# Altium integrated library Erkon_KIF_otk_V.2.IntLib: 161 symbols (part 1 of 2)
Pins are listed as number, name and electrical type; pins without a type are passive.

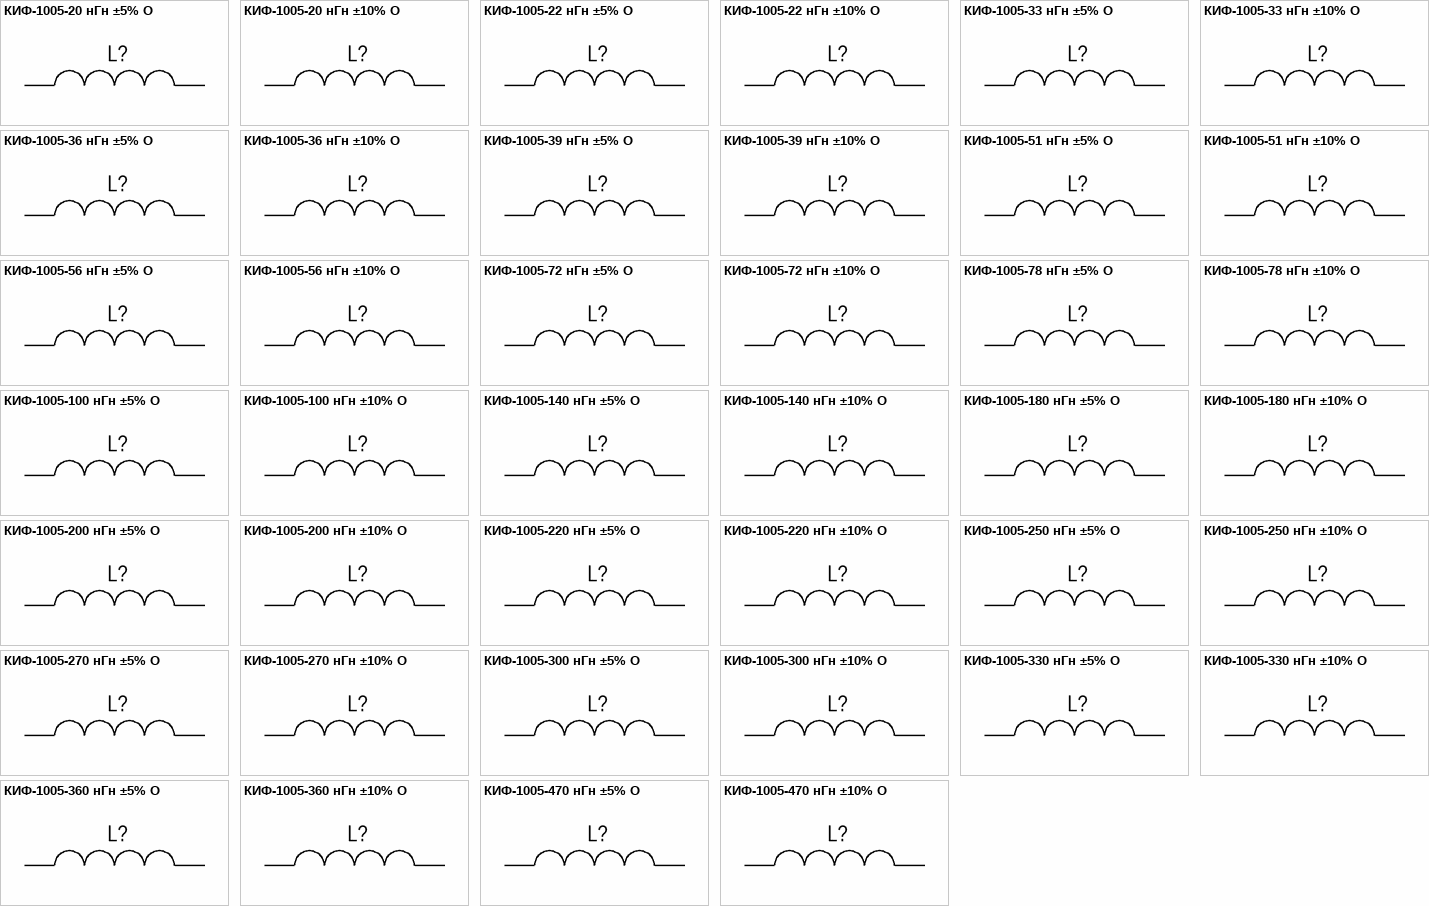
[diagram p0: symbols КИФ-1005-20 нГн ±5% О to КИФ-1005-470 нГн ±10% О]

## КИФ-1005-20 нГн ±5% О
designator L?, comment 20 нГн ±5%  (value not drawn)
Катушка индуктивности с ферритовым сердечником; Номиналиная индуктивность: 20 нГн; Добротность, не менее: 8; Резонансная частота, не менее: 2.6 ГГц; Сопротивление обмотки постоянноми току, не более: 0.07 Ом; Допустимый ток обмотки: 1600 мА; Диапазон рабочих температур: от -60 до +125 ℃; Упаковка: Катушка и лента; Типоразмер: 1005 (0402); Технология монтажа: SMT; Изготовитель: АО "НПО "ЭРКОН"
footprint КИФ-1005_О (Катушка индуктивности с ферритовым сердечником типоразмер 1005(0402))
pins: 1, 2

## КИФ-1005-20 нГн ±10% О
designator L?, comment 20 нГн ±10%  (value not drawn)
Катушка индуктивности с ферритовым сердечником; Номиналиная индуктивность: 20 нГн; Добротность, не менее: 8; Резонансная частота, не менее: 2.6 ГГц; Сопротивление обмотки постоянноми току, не более: 0.07 Ом; Допустимый ток обмотки: 1600 мА; Диапазон рабочих температур: от -60 до +125 ℃; Упаковка: Катушка и лента; Типоразмер: 1005 (0402); Технология монтажа: SMT; Изготовитель: АО "НПО "ЭРКОН"
footprint КИФ-1005_О (Катушка индуктивности с ферритовым сердечником типоразмер 1005(0402))
pins: 1, 2

## КИФ-1005-22 нГн ±5% О
designator L?, comment 22 нГн ±5%  (value not drawn)
Катушка индуктивности с ферритовым сердечником; Номиналиная индуктивность: 22 нГн; Добротность, не менее: 8; Резонансная частота, не менее: 2.5 ГГц; Сопротивление обмотки постоянноми току, не более: 0.08 Ом; Допустимый ток обмотки: 1300 мА; Диапазон рабочих температур: от -60 до +125 ℃; Упаковка: Катушка и лента; Типоразмер: 1005 (0402); Технология монтажа: SMT; Изготовитель: АО "НПО "ЭРКОН"
footprint КИФ-1005_О (Катушка индуктивности с ферритовым сердечником типоразмер 1005(0402))
pins: 1, 2

## КИФ-1005-22 нГн ±10% О
designator L?, comment 22 нГн ±10%  (value not drawn)
Катушка индуктивности с ферритовым сердечником; Номиналиная индуктивность: 22 нГн; Добротность, не менее: 8; Резонансная частота, не менее: 2.5 ГГц; Сопротивление обмотки постоянноми току, не более: 0.08 Ом; Допустимый ток обмотки: 1300 мА; Диапазон рабочих температур: от -60 до +125 ℃; Упаковка: Катушка и лента; Типоразмер: 1005 (0402); Технология монтажа: SMT; Изготовитель: АО "НПО "ЭРКОН"
footprint КИФ-1005_О (Катушка индуктивности с ферритовым сердечником типоразмер 1005(0402))
pins: 1, 2

## КИФ-1005-33 нГн ±5% О
designator L?, comment 33 нГн ±5%  (value not drawn)
Катушка индуктивности с ферритовым сердечником; Номиналиная индуктивность: 33 нГн; Добротность, не менее: 8; Резонансная частота, не менее: 2.3 ГГц; Сопротивление обмотки постоянноми току, не более: 0.08 Ом; Допустимый ток обмотки: 1400 мА; Диапазон рабочих температур: от -60 до +125 ℃; Упаковка: Катушка и лента; Типоразмер: 1005 (0402); Технология монтажа: SMT; Изготовитель: АО "НПО "ЭРКОН"
footprint КИФ-1005_О (Катушка индуктивности с ферритовым сердечником типоразмер 1005(0402))
pins: 1, 2

## КИФ-1005-33 нГн ±10% О
designator L?, comment 33 нГн ±10%  (value not drawn)
Катушка индуктивности с ферритовым сердечником; Номиналиная индуктивность: 33 нГн; Добротность, не менее: 8; Резонансная частота, не менее: 2.3 ГГц; Сопротивление обмотки постоянноми току, не более: 0.08 Ом; Допустимый ток обмотки: 1400 мА; Диапазон рабочих температур: от -60 до +125 ℃; Упаковка: Катушка и лента; Типоразмер: 1005 (0402); Технология монтажа: SMT; Изготовитель: АО "НПО "ЭРКОН"
footprint КИФ-1005_О (Катушка индуктивности с ферритовым сердечником типоразмер 1005(0402))
pins: 1, 2

## КИФ-1005-36 нГн ±5% О
designator L?, comment 36 нГн ±5%  (value not drawn)
Катушка индуктивности с ферритовым сердечником; Номиналиная индуктивность: 36 нГн; Добротность, не менее: 8; Резонансная частота, не менее: 2.3 ГГц; Сопротивление обмотки постоянноми току, не более: 0.1 Ом; Допустимый ток обмотки: 1300 мА; Диапазон рабочих температур: от -60 до +125 ℃; Упаковка: Катушка и лента; Типоразмер: 1005 (0402); Технология монтажа: SMT; Изготовитель: АО "НПО "ЭРКОН"
footprint КИФ-1005_О (Катушка индуктивности с ферритовым сердечником типоразмер 1005(0402))
pins: 1, 2

## КИФ-1005-36 нГн ±10% О
designator L?, comment 36 нГн ±10%  (value not drawn)
Катушка индуктивности с ферритовым сердечником; Номиналиная индуктивность: 36 нГн; Добротность, не менее: 8; Резонансная частота, не менее: 2.3 ГГц; Сопротивление обмотки постоянноми току, не более: 0.1 Ом; Допустимый ток обмотки: 1300 мА; Диапазон рабочих температур: от -60 до +125 ℃; Упаковка: Катушка и лента; Типоразмер: 1005 (0402); Технология монтажа: SMT; Изготовитель: АО "НПО "ЭРКОН"
footprint КИФ-1005_О (Катушка индуктивности с ферритовым сердечником типоразмер 1005(0402))
pins: 1, 2

## КИФ-1005-39 нГн ±5% О
designator L?, comment 39 нГн ±5%  (value not drawn)
Катушка индуктивности с ферритовым сердечником; Номиналиная индуктивность: 39 нГн; Добротность, не менее: 8; Резонансная частота, не менее: 2.2 ГГц; Сопротивление обмотки постоянноми току, не более: 0.14 Ом; Допустимый ток обмотки: 830 мА; Диапазон рабочих температур: от -60 до +125 ℃; Упаковка: Катушка и лента; Типоразмер: 1005 (0402); Технология монтажа: SMT; Изготовитель: АО "НПО "ЭРКОН"
footprint КИФ-1005_О (Катушка индуктивности с ферритовым сердечником типоразмер 1005(0402))
pins: 1, 2

## КИФ-1005-39 нГн ±10% О
designator L?, comment 39 нГн ±10%  (value not drawn)
Катушка индуктивности с ферритовым сердечником; Номиналиная индуктивность: 39 нГн; Добротность, не менее: 8; Резонансная частота, не менее: 2.2 ГГц; Сопротивление обмотки постоянноми току, не более: 0.14 Ом; Допустимый ток обмотки: 830 мА; Диапазон рабочих температур: от -60 до +125 ℃; Упаковка: Катушка и лента; Типоразмер: 1005 (0402); Технология монтажа: SMT; Изготовитель: АО "НПО "ЭРКОН"
footprint КИФ-1005_О (Катушка индуктивности с ферритовым сердечником типоразмер 1005(0402))
pins: 1, 2

## КИФ-1005-51 нГн ±5% О
designator L?, comment 51 нГн ±5%  (value not drawn)
Катушка индуктивности с ферритовым сердечником; Номиналиная индуктивность: 51 нГн; Добротность, не менее: 8; Резонансная частота, не менее: 1.93 ГГц; Сопротивление обмотки постоянноми току, не более: 0.11 Ом; Допустимый ток обмотки: 1100 мА; Диапазон рабочих температур: от -60 до +125 ℃; Упаковка: Катушка и лента; Типоразмер: 1005 (0402); Технология монтажа: SMT; Изготовитель: АО "НПО "ЭРКОН"
footprint КИФ-1005_О (Катушка индуктивности с ферритовым сердечником типоразмер 1005(0402))
pins: 1, 2

## КИФ-1005-51 нГн ±10% О
designator L?, comment 51 нГн ±10%  (value not drawn)
Катушка индуктивности с ферритовым сердечником; Номиналиная индуктивность: 51 нГн; Добротность, не менее: 8; Резонансная частота, не менее: 1.93 ГГц; Сопротивление обмотки постоянноми току, не более: 0.11 Ом; Допустимый ток обмотки: 1100 мА; Диапазон рабочих температур: от -60 до +125 ℃; Упаковка: Катушка и лента; Типоразмер: 1005 (0402); Технология монтажа: SMT; Изготовитель: АО "НПО "ЭРКОН"
footprint КИФ-1005_О (Катушка индуктивности с ферритовым сердечником типоразмер 1005(0402))
pins: 1, 2

## КИФ-1005-56 нГн ±5% О
designator L?, comment 56 нГн ±5%  (value not drawn)
Катушка индуктивности с ферритовым сердечником; Номиналиная индуктивность: 56 нГн; Добротность, не менее: 8; Резонансная частота, не менее: 1.90 ГГц; Сопротивление обмотки постоянноми току, не более: 0.12 Ом; Допустимый ток обмотки: 1000 мА; Диапазон рабочих температур: от -60 до +125 ℃; Упаковка: Катушка и лента; Типоразмер: 1005 (0402); Технология монтажа: SMT; Изготовитель: АО "НПО "ЭРКОН"
footprint КИФ-1005_О (Катушка индуктивности с ферритовым сердечником типоразмер 1005(0402))
pins: 1, 2

## КИФ-1005-56 нГн ±10% О
designator L?, comment 56 нГн ±10%  (value not drawn)
Катушка индуктивности с ферритовым сердечником; Номиналиная индуктивность: 56 нГн; Добротность, не менее: 8; Резонансная частота, не менее: 1.90 ГГц; Сопротивление обмотки постоянноми току, не более: 0.12 Ом; Допустимый ток обмотки: 1000 мА; Диапазон рабочих температур: от -60 до +125 ℃; Упаковка: Катушка и лента; Типоразмер: 1005 (0402); Технология монтажа: SMT; Изготовитель: АО "НПО "ЭРКОН"
footprint КИФ-1005_О (Катушка индуктивности с ферритовым сердечником типоразмер 1005(0402))
pins: 1, 2

## КИФ-1005-72 нГн ±5% О
designator L?, comment 72 нГн ±5%  (value not drawn)
Катушка индуктивности с ферритовым сердечником; Номиналиная индуктивность: 72 нГн; Добротность, не менее: 8; Резонансная частота, не менее: 1.65ГГц; Сопротивление обмотки постоянноми току, не более: 0.12 Ом; Допустимый ток обмотки: 1000 мА; Диапазон рабочих температур: от -60 до +125 ℃; Упаковка: Катушка и лента; Типоразмер: 1005 (0402); Технология монтажа: SMT; Изготовитель: АО "НПО "ЭРКОН"
footprint КИФ-1005_О (Катушка индуктивности с ферритовым сердечником типоразмер 1005(0402))
pins: 1, 2

## КИФ-1005-72 нГн ±10% О
designator L?, comment 72 нГн ±10%  (value not drawn)
Катушка индуктивности с ферритовым сердечником; Номиналиная индуктивность: 72 нГн; Добротность, не менее: 8; Резонансная частота, не менее: 1.65ГГц; Сопротивление обмотки постоянноми току, не более: 0.12 Ом; Допустимый ток обмотки: 1000 мА; Диапазон рабочих температур: от -60 до +125 ℃; Упаковка: Катушка и лента; Типоразмер: 1005 (0402); Технология монтажа: SMT; Изготовитель: АО "НПО "ЭРКОН"
footprint КИФ-1005_О (Катушка индуктивности с ферритовым сердечником типоразмер 1005(0402))
pins: 1, 2

## КИФ-1005-78 нГн ±5% О
designator L?, comment 78 нГн ±5%  (value not drawn)
Катушка индуктивности с ферритовым сердечником; Номиналиная индуктивность: 78 нГн; Добротность, не менее: 8; Резонансная частота, не менее: 1.6 ГГц; Сопротивление обмотки постоянноми току, не более: 0.16 Ом; Допустимый ток обмотки: 970 мА; Диапазон рабочих температур: от -60 до +125 ℃; Упаковка: Катушка и лента; Типоразмер: 1005 (0402); Технология монтажа: SMT; Изготовитель: АО "НПО "ЭРКОН"
footprint КИФ-1005_О (Катушка индуктивности с ферритовым сердечником типоразмер 1005(0402))
pins: 1, 2

## КИФ-1005-78 нГн ±10% О
designator L?, comment 78 нГн ±10%  (value not drawn)
Катушка индуктивности с ферритовым сердечником; Номиналиная индуктивность: 78 нГн; Добротность, не менее: 8; Резонансная частота, не менее: 1.6 ГГц; Сопротивление обмотки постоянноми току, не более: 0.16 Ом; Допустимый ток обмотки: 970 мА; Диапазон рабочих температур: от -60 до +125 ℃; Упаковка: Катушка и лента; Типоразмер: 1005 (0402); Технология монтажа: SMT; Изготовитель: АО "НПО "ЭРКОН"
footprint КИФ-1005_О (Катушка индуктивности с ферритовым сердечником типоразмер 1005(0402))
pins: 1, 2

## КИФ-1005-100 нГн ±5% О
designator L?, comment 100 нГн ±5%  (value not drawn)
Катушка индуктивности с ферритовым сердечником; Номиналиная индуктивность: 100 нГн; Добротность, не менее: 8; Резонансная частота, не менее: 1.4 ГГц; Сопротивление обмотки постоянноми току, не более: 0.19 Ом; Допустимый ток обмотки: 900 мА; Диапазон рабочих температур: от -60 до +125 ℃; Упаковка: Катушка и лента; Типоразмер: 1005 (0402); Технология монтажа: SMT; Изготовитель: АО "НПО "ЭРКОН"
footprint КИФ-1005_О (Катушка индуктивности с ферритовым сердечником типоразмер 1005(0402))
pins: 1, 2

## КИФ-1005-100 нГн ±10% О
designator L?, comment 100 нГн ±10%  (value not drawn)
Катушка индуктивности с ферритовым сердечником; Номиналиная индуктивность: 100 нГн; Добротность, не менее: 8; Резонансная частота, не менее: 1.4 ГГц; Сопротивление обмотки постоянноми току, не более: 0.19 Ом; Допустимый ток обмотки: 900 мА; Диапазон рабочих температур: от -60 до +125 ℃; Упаковка: Катушка и лента; Типоразмер: 1005 (0402); Технология монтажа: SMT; Изготовитель: АО "НПО "ЭРКОН"
footprint КИФ-1005_О (Катушка индуктивности с ферритовым сердечником типоразмер 1005(0402))
pins: 1, 2

## КИФ-1005-140 нГн ±5% О
designator L?, comment 140 нГн ±5%  (value not drawn)
Катушка индуктивности с ферритовым сердечником; Номиналиная индуктивность: 140 нГн; Добротность, не менее: 8; Резонансная частота, не менее: 1.22 ГГц; Сопротивление обмотки постоянноми току, не более: 0.31 Ом; Допустимый ток обмотки: 630 мА; Диапазон рабочих температур: от -60 до +125 ℃; Упаковка: Катушка и лента; Типоразмер: 1005 (0402); Технология монтажа: SMT; Изготовитель: АО "НПО "ЭРКОН"
footprint КИФ-1005_О (Катушка индуктивности с ферритовым сердечником типоразмер 1005(0402))
pins: 1, 2

## КИФ-1005-140 нГн ±10% О
designator L?, comment 140 нГн ±10%  (value not drawn)
Катушка индуктивности с ферритовым сердечником; Номиналиная индуктивность: 140 нГн; Добротность, не менее: 8; Резонансная частота, не менее: 1.22 ГГц; Сопротивление обмотки постоянноми току, не более: 0.31 Ом; Допустимый ток обмотки: 630 мА; Диапазон рабочих температур: от -60 до +125 ℃; Упаковка: Катушка и лента; Типоразмер: 1005 (0402); Технология монтажа: SMT; Изготовитель: АО "НПО "ЭРКОН"
footprint КИФ-1005_О (Катушка индуктивности с ферритовым сердечником типоразмер 1005(0402))
pins: 1, 2

## КИФ-1005-180 нГн ±5% О
designator L?, comment 180 нГн ±5%  (value not drawn)
Катушка индуктивности с ферритовым сердечником; Номиналиная индуктивность: 180 нГн; Добротность, не менее: 8; Резонансная частота, не менее: 1.15 ГГц; Сопротивление обмотки постоянноми току, не более: 0.34 Ом; Допустимый ток обмотки: 560 мА; Диапазон рабочих температур: от -60 до +125 ℃; Упаковка: Катушка и лента; Типоразмер: 1005 (0402); Технология монтажа: SMT; Изготовитель: АО "НПО "ЭРКОН"
footprint КИФ-1005_О (Катушка индуктивности с ферритовым сердечником типоразмер 1005(0402))
pins: 1, 2

## КИФ-1005-180 нГн ±10% О
designator L?, comment 180 нГн ±10%  (value not drawn)
Катушка индуктивности с ферритовым сердечником; Номиналиная индуктивность: 180 нГн; Добротность, не менее: 8; Резонансная частота, не менее: 1.15 ГГц; Сопротивление обмотки постоянноми току, не более: 0.34 Ом; Допустимый ток обмотки: 560 мА; Диапазон рабочих температур: от -60 до +125 ℃; Упаковка: Катушка и лента; Типоразмер: 1005 (0402); Технология монтажа: SMT; Изготовитель: АО "НПО "ЭРКОН"
footprint КИФ-1005_О (Катушка индуктивности с ферритовым сердечником типоразмер 1005(0402))
pins: 1, 2

## КИФ-1005-200 нГн ±5% О
designator L?, comment 200 нГн ±5%  (value not drawn)
Катушка индуктивности с ферритовым сердечником; Номиналиная индуктивность: 200 нГн; Добротность, не менее: 8; Резонансная частота, не менее: 1 ГГц; Сопротивление обмотки постоянноми току, не более: 0.53 Ом; Допустимый ток обмотки: 400 мА; Диапазон рабочих температур: от -60 до +125 ℃; Упаковка: Катушка и лента; Типоразмер: 1005 (0402); Технология монтажа: SMT; Изготовитель: АО "НПО "ЭРКОН"
footprint КИФ-1005_О (Катушка индуктивности с ферритовым сердечником типоразмер 1005(0402))
pins: 1, 2

## КИФ-1005-200 нГн ±10% О
designator L?, comment 200 нГн ±10%  (value not drawn)
Катушка индуктивности с ферритовым сердечником; Номиналиная индуктивность: 200 нГн; Добротность, не менее: 8; Резонансная частота, не менее: 1 ГГц; Сопротивление обмотки постоянноми току, не более: 0.53 Ом; Допустимый ток обмотки: 400 мА; Диапазон рабочих температур: от -60 до +125 ℃; Упаковка: Катушка и лента; Типоразмер: 1005 (0402); Технология монтажа: SMT; Изготовитель: АО "НПО "ЭРКОН"
footprint КИФ-1005_О (Катушка индуктивности с ферритовым сердечником типоразмер 1005(0402))
pins: 1, 2

## КИФ-1005-220 нГн ±5% О
designator L?, comment 220 нГн ±5%  (value not drawn)
Катушка индуктивности с ферритовым сердечником; Номиналиная индуктивность: 220 нГн; Добротность, не менее: 8; Резонансная частота, не менее: 1.15 ГГц; Сопротивление обмотки постоянноми току, не более: 0.64 Ом; Допустимый ток обмотки: 380 мА; Диапазон рабочих температур: от -60 до +125 ℃; Упаковка: Катушка и лента; Типоразмер: 1005 (0402); Технология монтажа: SMT; Изготовитель: АО "НПО "ЭРКОН"
footprint КИФ-1005_О (Катушка индуктивности с ферритовым сердечником типоразмер 1005(0402))
pins: 1, 2

## КИФ-1005-220 нГн ±10% О
designator L?, comment 220 нГн ±10%  (value not drawn)
Катушка индуктивности с ферритовым сердечником; Номиналиная индуктивность: 220 нГн; Добротность, не менее: 8; Резонансная частота, не менее: 1.15 ГГц; Сопротивление обмотки постоянноми току, не более: 0.64 Ом; Допустимый ток обмотки: 380 мА; Диапазон рабочих температур: от -60 до +125 ℃; Упаковка: Катушка и лента; Типоразмер: 1005 (0402); Технология монтажа: SMT; Изготовитель: АО "НПО "ЭРКОН"
footprint КИФ-1005_О (Катушка индуктивности с ферритовым сердечником типоразмер 1005(0402))
pins: 1, 2

## КИФ-1005-250 нГн ±5% О
designator L?, comment 250 нГн ±5%  (value not drawn)
Катушка индуктивности с ферритовым сердечником; Номиналиная индуктивность: 250 нГн; Добротность, не менее: 8; Резонансная частота, не менее: 0.9 ГГц; Сопротивление обмотки постоянноми току, не более: 0.43 Ом; Допустимый ток обмотки: 520 мА; Диапазон рабочих температур: от -60 до +125 ℃; Упаковка: Катушка и лента; Типоразмер: 1005 (0402); Технология монтажа: SMT; Изготовитель: АО "НПО "ЭРКОН"
footprint КИФ-1005_О (Катушка индуктивности с ферритовым сердечником типоразмер 1005(0402))
pins: 1, 2

## КИФ-1005-250 нГн ±10% О
designator L?, comment 250 нГн ±10%  (value not drawn)
Катушка индуктивности с ферритовым сердечником; Номиналиная индуктивность: 250 нГн; Добротность, не менее: 8; Резонансная частота, не менее: 0.9 ГГц; Сопротивление обмотки постоянноми току, не более: 0.43 Ом; Допустимый ток обмотки: 520 мА; Диапазон рабочих температур: от -60 до +125 ℃; Упаковка: Катушка и лента; Типоразмер: 1005 (0402); Технология монтажа: SMT; Изготовитель: АО "НПО "ЭРКОН"
footprint КИФ-1005_О (Катушка индуктивности с ферритовым сердечником типоразмер 1005(0402))
pins: 1, 2

## КИФ-1005-270 нГн ±5% О
designator L?, comment 270 нГн ±5%  (value not drawn)
Катушка индуктивности с ферритовым сердечником; Номиналиная индуктивность: 270 нГн; Добротность, не менее: 8; Резонансная частота, не менее: 0.86 ГГц; Сопротивление обмотки постоянноми току, не более: 0.66 Ом; Допустимый ток обмотки: 360 мА; Диапазон рабочих температур: от -60 до +125 ℃; Упаковка: Катушка и лента; Типоразмер: 1005 (0402); Технология монтажа: SMT; Изготовитель: АО "НПО "ЭРКОН"
footprint КИФ-1005_О (Катушка индуктивности с ферритовым сердечником типоразмер 1005(0402))
pins: 1, 2

## КИФ-1005-270 нГн ±10% О
designator L?, comment 270 нГн ±10%  (value not drawn)
Катушка индуктивности с ферритовым сердечником; Номиналиная индуктивность: 270 нГн; Добротность, не менее: 8; Резонансная частота, не менее: 0.86 ГГц; Сопротивление обмотки постоянноми току, не более: 0.66 Ом; Допустимый ток обмотки: 360 мА; Диапазон рабочих температур: от -60 до +125 ℃; Упаковка: Катушка и лента; Типоразмер: 1005 (0402); Технология монтажа: SMT; Изготовитель: АО "НПО "ЭРКОН"
footprint КИФ-1005_О (Катушка индуктивности с ферритовым сердечником типоразмер 1005(0402))
pins: 1, 2

## КИФ-1005-300 нГн ±5% О
designator L?, comment 300 нГн ±5%  (value not drawn)
Катушка индуктивности с ферритовым сердечником; Номиналиная индуктивность: 300 нГн; Добротность, не менее: 8; Резонансная частота, не менее: 0.86 ГГц; Сопротивление обмотки постоянноми току, не более: 0.5 Ом; Допустимый ток обмотки: 420 мА; Диапазон рабочих температур: от -60 до +125 ℃; Упаковка: Катушка и лента; Типоразмер: 1005 (0402); Технология монтажа: SMT; Изготовитель: АО "НПО "ЭРКОН"
footprint КИФ-1005_О (Катушка индуктивности с ферритовым сердечником типоразмер 1005(0402))
pins: 1, 2

## КИФ-1005-300 нГн ±10% О
designator L?, comment 300 нГн ±10%  (value not drawn)
Катушка индуктивности с ферритовым сердечником; Номиналиная индуктивность: 300 нГн; Добротность, не менее: 8; Резонансная частота, не менее: 0.86 ГГц; Сопротивление обмотки постоянноми току, не более: 0.5 Ом; Допустимый ток обмотки: 420 мА; Диапазон рабочих температур: от -60 до +125 ℃; Упаковка: Катушка и лента; Типоразмер: 1005 (0402); Технология монтажа: SMT; Изготовитель: АО "НПО "ЭРКОН"
footprint КИФ-1005_О (Катушка индуктивности с ферритовым сердечником типоразмер 1005(0402))
pins: 1, 2

## КИФ-1005-330 нГн ±5% О
designator L?, comment 330 нГн ±5%  (value not drawn)
Катушка индуктивности с ферритовым сердечником; Номиналиная индуктивность: 330 нГн; Добротность, не менее: 8; Резонансная частота, не менее: 0.82 ГГц; Сопротивление обмотки постоянноми току, не более: 0.67 Ом; Допустимый ток обмотки: 350 мА; Диапазон рабочих температур: от -60 до +125 ℃; Упаковка: Катушка и лента; Типоразмер: 1005 (0402); Технология монтажа: SMT; Изготовитель: АО "НПО "ЭРКОН"
footprint КИФ-1005_О (Катушка индуктивности с ферритовым сердечником типоразмер 1005(0402))
pins: 1, 2

## КИФ-1005-330 нГн ±10% О
designator L?, comment 330 нГн ±10%  (value not drawn)
Катушка индуктивности с ферритовым сердечником; Номиналиная индуктивность: 330 нГн; Добротность, не менее: 8; Резонансная частота, не менее: 0.82 ГГц; Сопротивление обмотки постоянноми току, не более: 0.67 Ом; Допустимый ток обмотки: 350 мА; Диапазон рабочих температур: от -60 до +125 ℃; Упаковка: Катушка и лента; Типоразмер: 1005 (0402); Технология монтажа: SMT; Изготовитель: АО "НПО "ЭРКОН"
footprint КИФ-1005_О (Катушка индуктивности с ферритовым сердечником типоразмер 1005(0402))
pins: 1, 2

## КИФ-1005-360 нГн ±5% О
designator L?, comment 360 нГн ±5%  (value not drawn)
Катушка индуктивности с ферритовым сердечником; Номиналиная индуктивность: 360 нГн; Добротность, не менее: 8; Резонансная частота, не менее: 0.81 ГГц; Сопротивление обмотки постоянноми току, не более: 0.75 Ом; Допустимый ток обмотки: 360 мА; Диапазон рабочих температур: от -60 до +125 ℃; Упаковка: Катушка и лента; Типоразмер: 1005 (0402); Технология монтажа: SMT; Изготовитель: АО "НПО "ЭРКОН"
footprint КИФ-1005_О (Катушка индуктивности с ферритовым сердечником типоразмер 1005(0402))
pins: 1, 2

## КИФ-1005-360 нГн ±10% О
designator L?, comment 360 нГн ±10%  (value not drawn)
Катушка индуктивности с ферритовым сердечником; Номиналиная индуктивность: 360 нГн; Добротность, не менее: 8; Резонансная частота, не менее: 0.81 ГГц; Сопротивление обмотки постоянноми току, не более: 0.75 Ом; Допустимый ток обмотки: 360 мА; Диапазон рабочих температур: от -60 до +125 ℃; Упаковка: Катушка и лента; Типоразмер: 1005 (0402); Технология монтажа: SMT; Изготовитель: АО "НПО "ЭРКОН"
footprint КИФ-1005_О (Катушка индуктивности с ферритовым сердечником типоразмер 1005(0402))
pins: 1, 2

## КИФ-1005-470 нГн ±5% О
designator L?, comment 470 нГн ±5%  (value not drawn)
Катушка индуктивности с ферритовым сердечником; Номиналиная индуктивность: 470 нГн; Добротность, не менее: 8; Резонансная частота, не менее: 0.7 ГГц; Сопротивление обмотки постоянноми току, не более: 1.42 Ом; Допустимый ток обмотки: 280 мА; Диапазон рабочих температур: от -60 до +125 ℃; Упаковка: Катушка и лента; Типоразмер: 1005 (0402); Технология монтажа: SMT; Изготовитель: АО "НПО "ЭРКОН"
footprint КИФ-1005_О (Катушка индуктивности с ферритовым сердечником типоразмер 1005(0402))
pins: 1, 2

## КИФ-1005-470 нГн ±10% О
designator L?, comment 470 нГн ±10%  (value not drawn)
Катушка индуктивности с ферритовым сердечником; Номиналиная индуктивность: 470 нГн; Допускаемое отклонение индуктивности: ±5%; Добротность, не менее: 8; Резонансная частота, не менее: 0.7 ГГц; Сопротивление обмотки постоянноми току, не более: 1.42 Ом; Допустимый ток обмотки: 280 мА; Диапазон рабочих температур: от -60 до +125 ℃; Упаковка: Катушка и лента; Типоразмер: 1005 (0402); Технология монтажа: SMT; Изготовитель: АО "НПО "ЭРКОН"
footprint КИФ-1005_О (Катушка индуктивности с ферритовым сердечником типоразмер 1005(0402))
pins: 1, 2


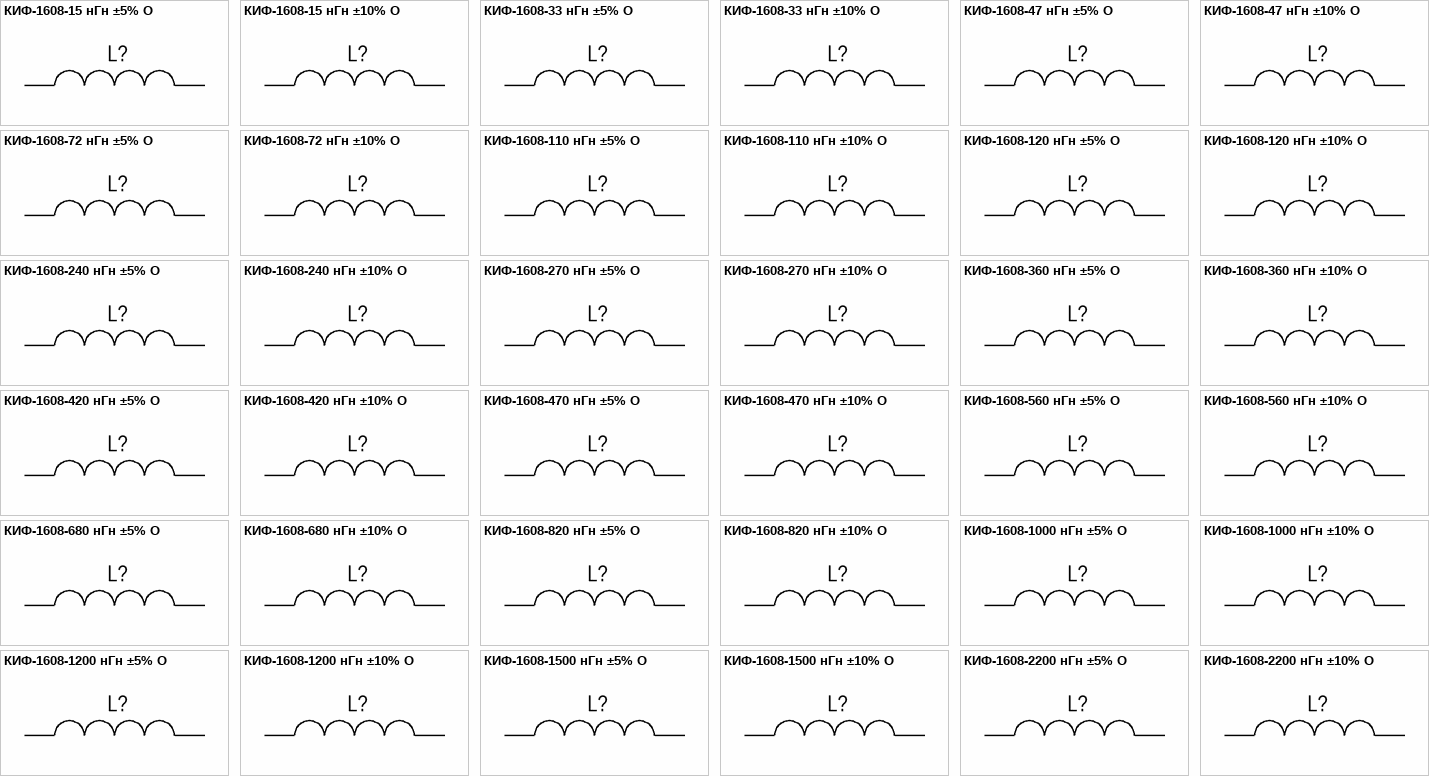
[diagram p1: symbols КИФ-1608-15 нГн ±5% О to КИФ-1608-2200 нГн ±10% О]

## КИФ-1608-15 нГн ±5% О
designator L?, comment 15 нГн ±5%  (value not drawn)
Катушка индуктивности с ферритовым сердечником; Номиналиная индуктивность: 15 нГн; Добротность, не менее: 10; Резонансная частота, не менее: 3.5 ГГц; Сопротивление обмотки постоянноми току, не более: 0.05 Ом; Допустимый ток обмотки: 2100 мА; Диапазон рабочих температур: от -60 до +125 ℃; Упаковка: Катушка и лента; Типоразмер: 1608 (0603); Технология монтажа: SMT; Изготовитель: АО "НПО "ЭРКОН"
footprint КИФ-1608-О (Катушка индуктивности с ферритовым сердечником типоразмер 1608(0805))
pins: 1, 2

## КИФ-1608-15 нГн ±10% О
designator L?, comment 15 нГн ±10%  (value not drawn)
Катушка индуктивности с ферритовым сердечником; Номиналиная индуктивность: 15 нГн; Добротность, не менее: 10; Резонансная частота, не менее: 3.5 ГГц; Сопротивление обмотки постоянноми току, не более: 0.05 Ом; Допустимый ток обмотки: 2100 мА; Диапазон рабочих температур: от -60 до +125 ℃; Упаковка: Катушка и лента; Типоразмер: 1608 (0603); Технология монтажа: SMT; Изготовитель: АО "НПО "ЭРКОН"
footprint КИФ-1608-О (Катушка индуктивности с ферритовым сердечником типоразмер 1608(0805))
pins: 1, 2

## КИФ-1608-33 нГн ±5% О
designator L?, comment 33 нГн ±5%  (value not drawn)
Катушка индуктивности с ферритовым сердечником; Номиналиная индуктивность: 33 нГн; Добротность, не менее: 10; Резонансная частота, не менее: 2.3 ГГц; Сопротивление обмотки постоянноми току, не более: 0.06 Ом; Допустимый ток обмотки: 1900 мА; Диапазон рабочих температур: от -60 до +125 ℃; Упаковка: Катушка и лента; Типоразмер: 1608 (0603); Технология монтажа: SMT; Изготовитель: АО "НПО "ЭРКОН"
footprint КИФ-1608-О (Катушка индуктивности с ферритовым сердечником типоразмер 1608(0805))
pins: 1, 2

## КИФ-1608-33 нГн ±10% О
designator L?, comment 33 нГн ±10%  (value not drawn)
Катушка индуктивности с ферритовым сердечником; Номиналиная индуктивность: 33 нГн; Добротность, не менее: 10; Резонансная частота, не менее: 2.3 ГГц; Сопротивление обмотки постоянноми току, не более: 0.06 Ом; Допустимый ток обмотки: 1900 мА; Диапазон рабочих температур: от -60 до +125 ℃; Упаковка: Катушка и лента; Типоразмер: 1608 (0603); Технология монтажа: SMT; Изготовитель: АО "НПО "ЭРКОН"
footprint КИФ-1608-О (Катушка индуктивности с ферритовым сердечником типоразмер 1608(0805))
pins: 1, 2

## КИФ-1608-47 нГн ±5% О
designator L?, comment 47 нГн ±5%  (value not drawn)
Катушка индуктивности с ферритовым сердечником; Номиналиная индуктивность: 47 нГн; Добротность, не менее: 10; Резонансная частота, не менее: 2.25 ГГц; Сопротивление обмотки постоянноми току, не более: 0.08 Ом; Допустимый ток обмотки: 1700 мА; Диапазон рабочих температур: от -60 до +125 ℃; Упаковка: Катушка и лента; Типоразмер: 1608 (0603); Технология монтажа: SMT; Изготовитель: АО "НПО "ЭРКОН"
footprint КИФ-1608-О (Катушка индуктивности с ферритовым сердечником типоразмер 1608(0805))
pins: 1, 2

## КИФ-1608-47 нГн ±10% О
designator L?, comment 47 нГн ±10%  (value not drawn)
Катушка индуктивности с ферритовым сердечником; Номиналиная индуктивность: 47 нГн; Добротность, не менее: 10; Резонансная частота, не менее: 2.25 ГГц; Сопротивление обмотки постоянноми току, не более: 0.08 Ом; Допустимый ток обмотки: 1700 мА; Диапазон рабочих температур: от -60 до +125 ℃; Упаковка: Катушка и лента; Типоразмер: 1608 (0603); Технология монтажа: SMT; Изготовитель: АО "НПО "ЭРКОН"
footprint КИФ-1608-О (Катушка индуктивности с ферритовым сердечником типоразмер 1608(0805))
pins: 1, 2

## КИФ-1608-72 нГн ±5% О
designator L?, comment 72 нГн ±5%  (value not drawn)
Катушка индуктивности с ферритовым сердечником; Номиналиная индуктивность: 72 нГн; Добротность, не менее: 10; Резонансная частота, не менее: 1.8 ГГц; Сопротивление обмотки постоянноми току, не более: 0.12 Ом; Допустимый ток обмотки: 1500 мА; Диапазон рабочих температур: от -60 до +125 ℃; Упаковка: Катушка и лента; Типоразмер: 1608 (0603); Технология монтажа: SMT; Изготовитель: АО "НПО "ЭРКОН"
footprint КИФ-1608-О (Катушка индуктивности с ферритовым сердечником типоразмер 1608(0805))
pins: 1, 2

## КИФ-1608-72 нГн ±10% О
designator L?, comment 72 нГн ±10%  (value not drawn)
Катушка индуктивности с ферритовым сердечником; Номиналиная индуктивность: 72 нГн; Добротность, не менее: 10; Резонансная частота, не менее: 1.8 ГГц; Сопротивление обмотки постоянноми току, не более: 0.12 Ом; Допустимый ток обмотки: 1500 мА; Диапазон рабочих температур: от -60 до +125 ℃; Упаковка: Катушка и лента; Типоразмер: 1608 (0603); Технология монтажа: SMT; Изготовитель: АО "НПО "ЭРКОН"
footprint КИФ-1608-О (Катушка индуктивности с ферритовым сердечником типоразмер 1608(0805))
pins: 1, 2

## КИФ-1608-110 нГн ±5% О
designator L?, comment 110 нГн ±5%  (value not drawn)
Катушка индуктивности с ферритовым сердечником; Номиналиная индуктивность: 110 нГн; Добротность, не менее: 10; Резонансная частота, не менее: 1.23 ГГц; Сопротивление обмотки постоянноми току, не более: 0.12 Ом; Допустимый ток обмотки: 1600 мА; Диапазон рабочих температур: от -60 до +125 ℃; Упаковка: Катушка и лента; Типоразмер: 1608 (0603); Технология монтажа: SMT; Изготовитель: АО "НПО "ЭРКОН"
footprint КИФ-1608-О (Катушка индуктивности с ферритовым сердечником типоразмер 1608(0805))
pins: 1, 2

## КИФ-1608-110 нГн ±10% О
designator L?, comment 110 нГн ±10%  (value not drawn)
Катушка индуктивности с ферритовым сердечником; Номиналиная индуктивность: 110 нГн; Добротность, не менее: 10; Резонансная частота, не менее: 1.23 ГГц; Сопротивление обмотки постоянноми току, не более: 0.12 Ом; Допустимый ток обмотки: 1600 мА; Диапазон рабочих температур: от -60 до +125 ℃; Упаковка: Катушка и лента; Типоразмер: 1608 (0603); Технология монтажа: SMT; Изготовитель: АО "НПО "ЭРКОН"
footprint КИФ-1608-О (Катушка индуктивности с ферритовым сердечником типоразмер 1608(0805))
pins: 1, 2

## КИФ-1608-120 нГн ±5% О
designator L?, comment 120 нГн ±5%  (value not drawn)
Катушка индуктивности с ферритовым сердечником; Номиналиная индуктивность: 120 нГн; Добротность, не менее: 10; Резонансная частота, не менее: 1.15 ГГц; Сопротивление обмотки постоянноми току, не более: 0.17 Ом; Допустимый ток обмотки: 1400 мА; Диапазон рабочих температур: от -60 до +125 ℃; Упаковка: Катушка и лента; Типоразмер: 1608 (0603); Технология монтажа: SMT; Изготовитель: АО "НПО "ЭРКОН"
footprint КИФ-1608-О (Катушка индуктивности с ферритовым сердечником типоразмер 1608(0805))
pins: 1, 2

## КИФ-1608-120 нГн ±10% О
designator L?, comment 120 нГн ±10%  (value not drawn)
Катушка индуктивности с ферритовым сердечником; Номиналиная индуктивность: 120 нГн; Добротность, не менее: 10; Резонансная частота, не менее: 1.15 ГГц; Сопротивление обмотки постоянноми току, не более: 0.17 Ом; Допустимый ток обмотки: 1400 мА; Диапазон рабочих температур: от -60 до +125 ℃; Упаковка: Катушка и лента; Типоразмер: 1608 (0603); Технология монтажа: SMT; Изготовитель: АО "НПО "ЭРКОН"
footprint КИФ-1608-О (Катушка индуктивности с ферритовым сердечником типоразмер 1608(0805))
pins: 1, 2

## КИФ-1608-240 нГн ±5% О
designator L?, comment 240 нГн ±5%  (value not drawn)
Катушка индуктивности с ферритовым сердечником; Номиналиная индуктивность: 240 нГн; Добротность, не менее: 10; Резонансная частота, не менее: 0.9 ГГц; Сопротивление обмотки постоянноми току, не более: 0.27 Ом; Допустимый ток обмотки: 850 мА; Диапазон рабочих температур: от -60 до +125 ℃; Упаковка: Катушка и лента; Типоразмер: 1608 (0603); Технология монтажа: SMT; Изготовитель: АО "НПО "ЭРКОН"
footprint КИФ-1608-О (Катушка индуктивности с ферритовым сердечником типоразмер 1608(0805))
pins: 1, 2

## КИФ-1608-240 нГн ±10% О
designator L?, comment 240 нГн ±10%  (value not drawn)
Катушка индуктивности с ферритовым сердечником; Номиналиная индуктивность: 240 нГн; Добротность, не менее: 10; Резонансная частота, не менее: 0.9 ГГц; Сопротивление обмотки постоянноми току, не более: 0.27 Ом; Допустимый ток обмотки: 850 мА; Диапазон рабочих температур: от -60 до +125 ℃; Упаковка: Катушка и лента; Типоразмер: 1608 (0603); Технология монтажа: SMT; Изготовитель: АО "НПО "ЭРКОН"
footprint КИФ-1608-О (Катушка индуктивности с ферритовым сердечником типоразмер 1608(0805))
pins: 1, 2

## КИФ-1608-270 нГн ±5% О
designator L?, comment 270 нГн ±5%  (value not drawn)
Катушка индуктивности с ферритовым сердечником; Номиналиная индуктивность: 270 нГн; Добротность, не менее: 10; Резонансная частота, не менее: 0.75 ГГц; Сопротивление обмотки постоянноми току, не более: 0.28 Ом; Допустимый ток обмотки: 680 мА; Диапазон рабочих температур: от -60 до +125 ℃; Упаковка: Катушка и лента; Типоразмер: 1608 (0603); Технология монтажа: SMT; Изготовитель: АО "НПО "ЭРКОН"
footprint КИФ-1608-О (Катушка индуктивности с ферритовым сердечником типоразмер 1608(0805))
pins: 1, 2

## КИФ-1608-270 нГн ±10% О
designator L?, comment 270 нГн ±10%  (value not drawn)
Катушка индуктивности с ферритовым сердечником; Номиналиная индуктивность: 270 нГн; Добротность, не менее: 10; Резонансная частота, не менее: 0.75 ГГц; Сопротивление обмотки постоянноми току, не более: 0.28 Ом; Допустимый ток обмотки: 680 мА; Диапазон рабочих температур: от -60 до +125 ℃; Упаковка: Катушка и лента; Типоразмер: 1608 (0603); Технология монтажа: SMT; Изготовитель: АО "НПО "ЭРКОН"
footprint КИФ-1608-О (Катушка индуктивности с ферритовым сердечником типоразмер 1608(0805))
pins: 1, 2

## КИФ-1608-360 нГн ±5% О
designator L?, comment 360 нГн ±5%  (value not drawn)
Катушка индуктивности с ферритовым сердечником; Номиналиная индуктивность: 360 нГн; Добротность, не менее: 10; Резонансная частота, не менее: 0.7 ГГц; Сопротивление обмотки постоянноми току, не более: 0.33 Ом; Допустимый ток обмотки: 650 мА; Диапазон рабочих температур: от -60 до +125 ℃; Упаковка: Катушка и лента; Типоразмер: 1608 (0603); Технология монтажа: SMT; Изготовитель: АО "НПО "ЭРКОН"
footprint КИФ-1608-О (Катушка индуктивности с ферритовым сердечником типоразмер 1608(0805))
pins: 1, 2

## КИФ-1608-360 нГн ±10% О
designator L?, comment 360 нГн ±10%  (value not drawn)
Катушка индуктивности с ферритовым сердечником; Номиналиная индуктивность: 360 нГн; Добротность, не менее: 10; Резонансная частота, не менее: 0.7 ГГц; Сопротивление обмотки постоянноми току, не более: 0.33 Ом; Допустимый ток обмотки: 650 мА; Диапазон рабочих температур: от -60 до +125 ℃; Упаковка: Катушка и лента; Типоразмер: 1608 (0603); Технология монтажа: SMT; Изготовитель: АО "НПО "ЭРКОН"
footprint КИФ-1608-О (Катушка индуктивности с ферритовым сердечником типоразмер 1608(0805))
pins: 1, 2

## КИФ-1608-420 нГн ±5% О
designator L?, comment 420 нГн ±5%  (value not drawn)
Катушка индуктивности с ферритовым сердечником; Номиналиная индуктивность: 420 нГн; Добротность, не менее: 10; Резонансная частота, не менее: 0.685 ГГц; Сопротивление обмотки постоянноми току, не более: 0.5 Ом; Допустимый ток обмотки: 610 мА; Диапазон рабочих температур: от -60 до +125 ℃; Упаковка: Катушка и лента; Типоразмер: 1608 (0603); Технология монтажа: SMT; Изготовитель: АО "НПО "ЭРКОН"
footprint КИФ-1608-О (Катушка индуктивности с ферритовым сердечником типоразмер 1608(0805))
pins: 1, 2

## КИФ-1608-420 нГн ±10% О
designator L?, comment 420 нГн ±10%  (value not drawn)
Катушка индуктивности с ферритовым сердечником; Номиналиная индуктивность: 420 нГн; Добротность, не менее: 10; Резонансная частота, не менее: 0.685 ГГц; Сопротивление обмотки постоянноми току, не более: 0.5 Ом; Допустимый ток обмотки: 610 мА; Диапазон рабочих температур: от -60 до +125 ℃; Упаковка: Катушка и лента; Типоразмер: 1608 (0603); Технология монтажа: SMT; Изготовитель: АО "НПО "ЭРКОН"
footprint КИФ-1608-О (Катушка индуктивности с ферритовым сердечником типоразмер 1608(0805))
pins: 1, 2

## КИФ-1608-470 нГн ±5% О
designator L?, comment 470 нГн ±5%  (value not drawn)
Катушка индуктивности с ферритовым сердечником; Номиналиная индуктивность: 470 нГн; Добротность, не менее: 10; Резонансная частота, не менее: 0.575 ГГц; Сопротивление обмотки постоянноми току, не более: 0.58 Ом; Допустимый ток обмотки: 610 мА; Диапазон рабочих температур: от -60 до +125 ℃; Упаковка: Катушка и лента; Типоразмер: 1608 (0603); Технология монтажа: SMT; Изготовитель: АО "НПО "ЭРКОН"
footprint КИФ-1608-О (Катушка индуктивности с ферритовым сердечником типоразмер 1608(0805))
pins: 1, 2

## КИФ-1608-470 нГн ±10% О
designator L?, comment 470 нГн ±10%  (value not drawn)
Катушка индуктивности с ферритовым сердечником; Номиналиная индуктивность: 470 нГн; Добротность, не менее: 10; Резонансная частота, не менее: 0.575 ГГц; Сопротивление обмотки постоянноми току, не более: 0.58 Ом; Допустимый ток обмотки: 610 мА; Диапазон рабочих температур: от -60 до +125 ℃; Упаковка: Катушка и лента; Типоразмер: 1608 (0603); Технология монтажа: SMT; Изготовитель: АО "НПО "ЭРКОН"
footprint КИФ-1608-О (Катушка индуктивности с ферритовым сердечником типоразмер 1608(0805))
pins: 1, 2

## КИФ-1608-560 нГн ±5% О
designator L?, comment 560 нГн ±5%  (value not drawn)
Катушка индуктивности с ферритовым сердечником; Номиналиная индуктивность: 560 нГн; Добротность, не менее: 10; Резонансная частота, не менее: 0.515 ГГц; Сопротивление обмотки постоянноми току, не более: 0.6 Ом; Допустимый ток обмотки: 530 мА; Диапазон рабочих температур: от -60 до +125 ℃; Упаковка: Катушка и лента; Типоразмер: 1608 (0603); Технология монтажа: SMT; Изготовитель: АО "НПО "ЭРКОН"
footprint КИФ-1608-О (Катушка индуктивности с ферритовым сердечником типоразмер 1608(0805))
pins: 1, 2

## КИФ-1608-560 нГн ±10% О
designator L?, comment 560 нГн ±10%  (value not drawn)
Катушка индуктивности с ферритовым сердечником; Номиналиная индуктивность: 560 нГн; Добротность, не менее: 10; Резонансная частота, не менее: 0.515 ГГц; Сопротивление обмотки постоянноми току, не более: 0.6 Ом; Допустимый ток обмотки: 530 мА; Диапазон рабочих температур: от -60 до +125 ℃; Упаковка: Катушка и лента; Типоразмер: 1608 (0603); Технология монтажа: SMT; Изготовитель: АО "НПО "ЭРКОН"
footprint КИФ-1608-О (Катушка индуктивности с ферритовым сердечником типоразмер 1608(0805))
pins: 1, 2

## КИФ-1608-680 нГн ±5% О
designator L?, comment 680 нГн ±5%  (value not drawn)
Катушка индуктивности с ферритовым сердечником; Номиналиная индуктивность: 680 нГн; Добротность, не менее: 10; Резонансная частота, не менее: 0.53 ГГц; Сопротивление обмотки постоянноми току, не более: 0.65 Ом; Допустимый ток обмотки: 490 мА; Диапазон рабочих температур: от -60 до +125 ℃; Упаковка: Катушка и лента; Типоразмер: 1608 (0603); Технология монтажа: SMT; Изготовитель: АО "НПО "ЭРКОН"
footprint КИФ-1608-О (Катушка индуктивности с ферритовым сердечником типоразмер 1608(0805))
pins: 1, 2

## КИФ-1608-680 нГн ±10% О
designator L?, comment 680 нГн ±10%  (value not drawn)
Катушка индуктивности с ферритовым сердечником; Номиналиная индуктивность: 680 нГн; Добротность, не менее: 10; Резонансная частота, не менее: 0.53 ГГц; Сопротивление обмотки постоянноми току, не более: 0.65 Ом; Допустимый ток обмотки: 490 мА; Диапазон рабочих температур: от -60 до +125 ℃; Упаковка: Катушка и лента; Типоразмер: 1608 (0603); Технология монтажа: SMT; Изготовитель: АО "НПО "ЭРКОН"
footprint КИФ-1608-О (Катушка индуктивности с ферритовым сердечником типоразмер 1608(0805))
pins: 1, 2

## КИФ-1608-820 нГн ±5% О
designator L?, comment 820 нГн ±5%  (value not drawn)
Катушка индуктивности с ферритовым сердечником; Номиналиная индуктивность: 820 нГн; Добротность, не менее: 10; Резонансная частота, не менее: 0.325 ГГц; Сопротивление обмотки постоянноми току, не более: 0.75 Ом; Допустимый ток обмотки: 420 мА; Диапазон рабочих температур: от -60 до +125 ℃; Упаковка: Катушка и лента; Типоразмер: 1608 (0603); Технология монтажа: SMT; Изготовитель: АО "НПО "ЭРКОН"
footprint КИФ-1608-О (Катушка индуктивности с ферритовым сердечником типоразмер 1608(0805))
pins: 1, 2

## КИФ-1608-820 нГн ±10% О
designator L?, comment 820 нГн ±10%  (value not drawn)
Катушка индуктивности с ферритовым сердечником; Номиналиная индуктивность: 820 нГн; Добротность, не менее: 10; Резонансная частота, не менее: 0.325 ГГц; Сопротивление обмотки постоянноми току, не более: 0.75 Ом; Допустимый ток обмотки: 420 мА; Диапазон рабочих температур: от -60 до +125 ℃; Упаковка: Катушка и лента; Типоразмер: 1608 (0603); Технология монтажа: SMT; Изготовитель: АО "НПО "ЭРКОН"
footprint КИФ-1608-О (Катушка индуктивности с ферритовым сердечником типоразмер 1608(0805))
pins: 1, 2

## КИФ-1608-1000 нГн ±5% О
designator L?, comment 1000 нГн ±5%  (value not drawn)
Катушка индуктивности с ферритовым сердечником; Добротность, не менее: 10; Резонансная частота, не менее: 0.4 ГГц; Сопротивление обмотки постоянноми току, не более: 0.8 Ом; Допустимый ток обмотки: 400 мА; Диапазон рабочих температур: от -60 до +125 ℃; Упаковка: Катушка и лента; Типоразмер: 1608 (0603); Технология монтажа: SMT; Изготовитель: АО "НПО "ЭРКОН"
footprint КИФ-1608-О (Катушка индуктивности с ферритовым сердечником типоразмер 1608(0805))
pins: 1, 2

## КИФ-1608-1000 нГн ±10% О
designator L?, comment 1000 нГн ±10%  (value not drawn)
Катушка индуктивности с ферритовым сердечником; Добротность, не менее: 10; Резонансная частота, не менее: 0.4 ГГц; Сопротивление обмотки постоянноми току, не более: 0.8 Ом; Допустимый ток обмотки: 400 мА; Диапазон рабочих температур: от -60 до +125 ℃; Упаковка: Катушка и лента; Типоразмер: 1608 (0603); Технология монтажа: SMT; Изготовитель: АО "НПО "ЭРКОН"
footprint КИФ-1608-О (Катушка индуктивности с ферритовым сердечником типоразмер 1608(0805))
pins: 1, 2

## КИФ-1608-1200 нГн ±5% О
designator L?, comment 1200 нГн ±5%  (value not drawn)
Катушка индуктивности с ферритовым сердечником; Добротность, не менее: 10; Резонансная частота, не менее: 0.4 ГГц; Сопротивление обмотки постоянноми току, не более: 1.4 Ом; Допустимый ток обмотки: 300 мА; Диапазон рабочих температур: от -60 до +125 ℃; Упаковка: Катушка и лента; Типоразмер: 1608 (0603); Технология монтажа: SMT; Изготовитель: АО "НПО "ЭРКОН"
footprint КИФ-1608-О (Катушка индуктивности с ферритовым сердечником типоразмер 1608(0805))
pins: 1, 2

## КИФ-1608-1200 нГн ±10% О
designator L?, comment 1200 нГн ±10%  (value not drawn)
Катушка индуктивности с ферритовым сердечником; Добротность, не менее: 10; Резонансная частота, не менее: 0.4 ГГц; Сопротивление обмотки постоянноми току, не более: 1.4 Ом; Допустимый ток обмотки: 300 мА; Диапазон рабочих температур: от -60 до +125 ℃; Упаковка: Катушка и лента; Типоразмер: 1608 (0603); Технология монтажа: SMT; Изготовитель: АО "НПО "ЭРКОН"
footprint КИФ-1608-О (Катушка индуктивности с ферритовым сердечником типоразмер 1608(0805))
pins: 1, 2

## КИФ-1608-1500 нГн ±5% О
designator L?, comment 1500 нГн ±5%  (value not drawn)
Катушка индуктивности с ферритовым сердечником; Добротность, не менее: 10; Резонансная частота, не менее: 0.4 ГГц; Сопротивление обмотки постоянноми току, не более: 1.5 Ом; Допустимый ток обмотки: 250 мА; Диапазон рабочих температур: от -60 до +125 ℃; Упаковка: Катушка и лента; Типоразмер: 1608 (0603); Технология монтажа: SMT; Изготовитель: АО "НПО "ЭРКОН"
footprint КИФ-1608-О (Катушка индуктивности с ферритовым сердечником типоразмер 1608(0805))
pins: 1, 2

## КИФ-1608-1500 нГн ±10% О
designator L?, comment 1500 нГн ±10%  (value not drawn)
Катушка индуктивности с ферритовым сердечником; Добротность, не менее: 10; Резонансная частота, не менее: 0.4 ГГц; Сопротивление обмотки постоянноми току, не более: 1.5 Ом; Допустимый ток обмотки: 250 мА; Диапазон рабочих температур: от -60 до +125 ℃; Упаковка: Катушка и лента; Типоразмер: 1608 (0603); Технология монтажа: SMT; Изготовитель: АО "НПО "ЭРКОН"
footprint КИФ-1608-О (Катушка индуктивности с ферритовым сердечником типоразмер 1608(0805))
pins: 1, 2

## КИФ-1608-2200 нГн ±5% О
designator L?, comment 2200 нГн ±5%  (value not drawn)
Катушка индуктивности с ферритовым сердечником; Добротность, не менее: 10; Резонансная частота, не менее: 0.085 ГГц; Сопротивление обмотки постоянноми току, не более: 3 Ом; Допустимый ток обмотки: 320 мА; Диапазон рабочих температур: от -60 до +125 ℃; Упаковка: Катушка и лента; Типоразмер: 1608 (0603); Технология монтажа: SMT; Изготовитель: АО "НПО "ЭРКОН"
footprint КИФ-1608-О (Катушка индуктивности с ферритовым сердечником типоразмер 1608(0805))
pins: 1, 2

## КИФ-1608-2200 нГн ±10% О
designator L?, comment 2200 нГн ±10%  (value not drawn)
Катушка индуктивности с ферритовым сердечником; Добротность, не менее: 10; Резонансная частота, не менее: 0.085 ГГц; Сопротивление обмотки постоянноми току, не более: 3 Ом; Допустимый ток обмотки: 320 мА; Диапазон рабочих температур: от -60 до +125 ℃; Упаковка: Катушка и лента; Типоразмер: 1608 (0603); Технология монтажа: SMT; Изготовитель: АО "НПО "ЭРКОН"
footprint КИФ-1608-О (Катушка индуктивности с ферритовым сердечником типоразмер 1608(0805))
pins: 1, 2


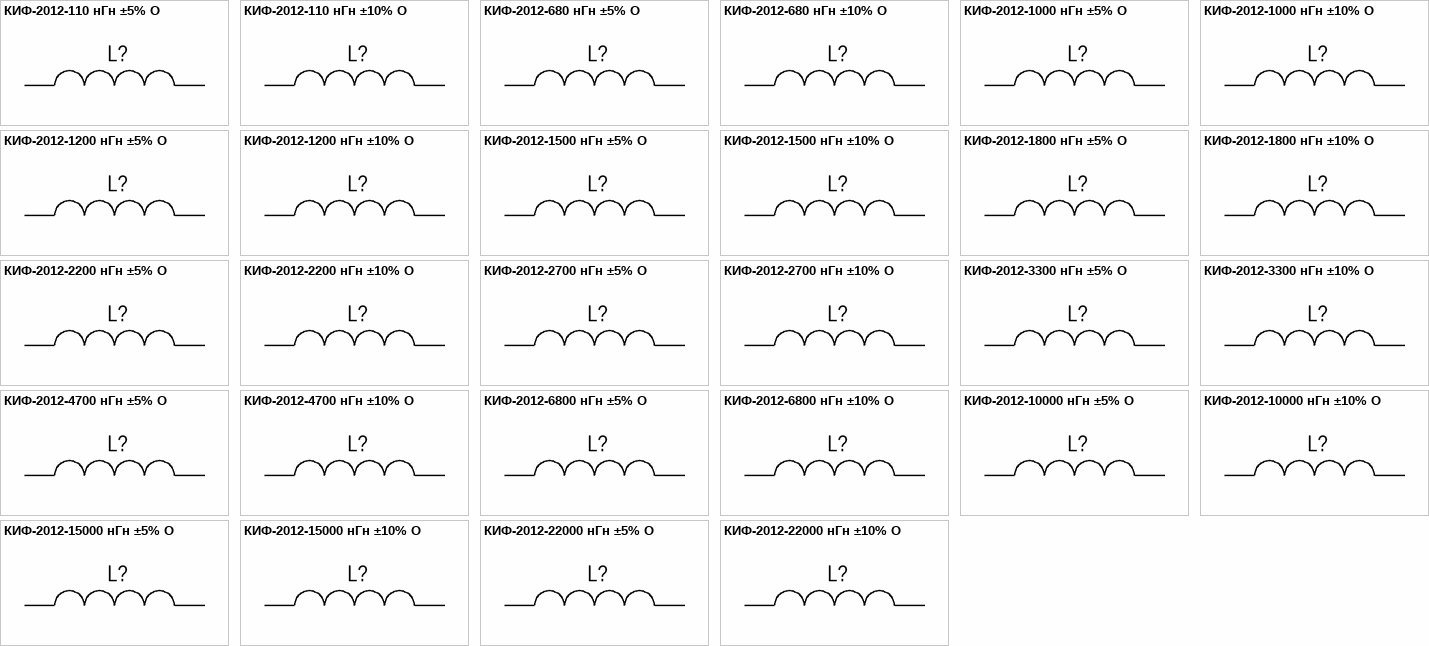
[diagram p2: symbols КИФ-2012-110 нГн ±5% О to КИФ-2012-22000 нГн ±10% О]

## КИФ-2012-110 нГн ±5% О
designator L?, comment 110 нГн ±5%  (value not drawn)
Катушка индуктивности с ферритовым сердечником; Номиналиная индуктивность: 110 нГн; Добротность, не менее: 13; Резонансная частота, не менее: 1,26 ГГц; Сопротивление обмотки постоянноми току, не более: 0.09 Ом; Допустимый ток обмотки: 940 мА; Диапазон рабочих температур: от -60 до +125 ℃; Упаковка: Катушка и лента; Типоразмер: 2012 (0805); Технология монтажа: SMT; Изготовитель: АО "НПО "ЭРКОН"
footprint КИФ-2012-O (Катушка индуктивности с ферритовым сердечником типоразмер 2012(0805))
pins: 1, 2

## КИФ-2012-110 нГн ±10% О
designator L?, comment 110 нГн ±10%  (value not drawn)
Катушка индуктивности с ферритовым сердечником; Номиналиная индуктивность: 110 нГн; Добротность, не менее: 13; Резонансная частота, не менее: 1,26 ГГц; Сопротивление обмотки постоянноми току, не более: 0.09 Ом; Допустимый ток обмотки: 940 мА; Диапазон рабочих температур: от -60 до +125 ℃; Упаковка: Катушка и лента; Типоразмер: 2012 (0805); Технология монтажа: SMT; Изготовитель: АО "НПО "ЭРКОН"
footprint КИФ-2012-O (Катушка индуктивности с ферритовым сердечником типоразмер 2012(0805))
pins: 1, 2

## КИФ-2012-680 нГн ±5% О
designator L?, comment 680 нГн ±5%  (value not drawn)
Катушка индуктивности с ферритовым сердечником; Номиналиная индуктивность: 680 нГн; Добротность, не менее: 13; Резонансная частота, не менее: 0,425 ГГц; Сопротивление обмотки постоянноми току, не более: 0.7 Ом; Допустимый ток обмотки: 660 мА; Диапазон рабочих температур: от -60 до +125 ℃; Упаковка: Катушка и лента; Типоразмер: 2012 (0805); Технология монтажа: SMT; Изготовитель: АО "НПО "ЭРКОН"
footprint КИФ-2012-O (Катушка индуктивности с ферритовым сердечником типоразмер 2012(0805))
pins: 1, 2

## КИФ-2012-680 нГн ±10% О
designator L?, comment 680 нГн ±10%  (value not drawn)
Катушка индуктивности с ферритовым сердечником; Номиналиная индуктивность: 680 нГн; Добротность, не менее: 13; Резонансная частота, не менее: 0,425 ГГц; Сопротивление обмотки постоянноми току, не более: 0.7 Ом; Допустимый ток обмотки: 660 мА; Диапазон рабочих температур: от -60 до +125 ℃; Упаковка: Катушка и лента; Типоразмер: 2012 (0805); Технология монтажа: SMT; Изготовитель: АО "НПО "ЭРКОН"
footprint КИФ-2012-O (Катушка индуктивности с ферритовым сердечником типоразмер 2012(0805))
pins: 1, 2

## КИФ-2012-1000 нГн ±5% О
designator L?, comment 1000 нГн ±5%  (value not drawn)
Катушка индуктивности с ферритовым сердечником; Добротность, не менее: 13; Резонансная частота, не менее: 0,355 ГГц; Сопротивление обмотки постоянноми току, не более: 0.6 Ом; Допустимый ток обмотки: 650 мА; Диапазон рабочих температур: от -60 до +125 ℃; Упаковка: Катушка и лента; Типоразмер: 2012 (0805); Технология монтажа: SMT; Изготовитель: АО "НПО "ЭРКОН"
footprint КИФ-2012-O (Катушка индуктивности с ферритовым сердечником типоразмер 2012(0805))
pins: 1, 2

## КИФ-2012-1000 нГн ±10% О
designator L?, comment 1000 нГн ±10%  (value not drawn)
Катушка индуктивности с ферритовым сердечником; Добротность, не менее: 13; Резонансная частота, не менее: 0,355 ГГц; Сопротивление обмотки постоянноми току, не более: 0.6 Ом; Допустимый ток обмотки: 650 мА; Диапазон рабочих температур: от -60 до +125 ℃; Упаковка: Катушка и лента; Типоразмер: 2012 (0805); Технология монтажа: SMT; Изготовитель: АО "НПО "ЭРКОН"
footprint КИФ-2012-O (Катушка индуктивности с ферритовым сердечником типоразмер 2012(0805))
pins: 1, 2

## КИФ-2012-1200 нГн ±5% О
designator L?, comment 1200 нГн ±5%  (value not drawn)
Катушка индуктивности с ферритовым сердечником; Добротность, не менее: 13; Резонансная частота, не менее: 0,375 ГГц; Сопротивление обмотки постоянноми току, не более: 0.96 Ом; Допустимый ток обмотки: 440 мА; Диапазон рабочих температур: от -60 до +125 ℃; Упаковка: Катушка и лента; Типоразмер: 2012 (0805); Технология монтажа: SMT; Изготовитель: АО "НПО "ЭРКОН"
footprint КИФ-2012-O (Катушка индуктивности с ферритовым сердечником типоразмер 2012(0805))
pins: 1, 2

## КИФ-2012-1200 нГн ±10% О
designator L?, comment 1200 нГн ±10%  (value not drawn)
Катушка индуктивности с ферритовым сердечником; Добротность, не менее: 13; Резонансная частота, не менее: 0,375 ГГц; Сопротивление обмотки постоянноми току, не более: 0.96 Ом; Допустимый ток обмотки: 440 мА; Диапазон рабочих температур: от -60 до +125 ℃; Упаковка: Катушка и лента; Типоразмер: 2012 (0805); Технология монтажа: SMT; Изготовитель: АО "НПО "ЭРКОН"
footprint КИФ-2012-O (Катушка индуктивности с ферритовым сердечником типоразмер 2012(0805))
pins: 1, 2

## КИФ-2012-1500 нГн ±5% О
designator L?, comment 1500 нГн ±5%  (value not drawn)
Катушка индуктивности с ферритовым сердечником; Добротность, не менее: 13; Резонансная частота, не менее: 0,285 ГГц; Сопротивление обмотки постоянноми току, не более: 1.12 Ом; Допустимый ток обмотки: 390 мА; Диапазон рабочих температур: от -60 до +125 ℃; Упаковка: Катушка и лента; Типоразмер: 2012 (0805); Технология монтажа: SMT; Изготовитель: АО "НПО "ЭРКОН"
footprint КИФ-2012-O (Катушка индуктивности с ферритовым сердечником типоразмер 2012(0805))
pins: 1, 2

## КИФ-2012-1500 нГн ±10% О
designator L?, comment 1500 нГн ±10%  (value not drawn)
Катушка индуктивности с ферритовым сердечником; Добротность, не менее: 13; Резонансная частота, не менее: 0,285 ГГц; Сопротивление обмотки постоянноми току, не более: 1.12 Ом; Допустимый ток обмотки: 390 мА; Диапазон рабочих температур: от -60 до +125 ℃; Упаковка: Катушка и лента; Типоразмер: 2012 (0805); Технология монтажа: SMT; Изготовитель: АО "НПО "ЭРКОН"
footprint КИФ-2012-O (Катушка индуктивности с ферритовым сердечником типоразмер 2012(0805))
pins: 1, 2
